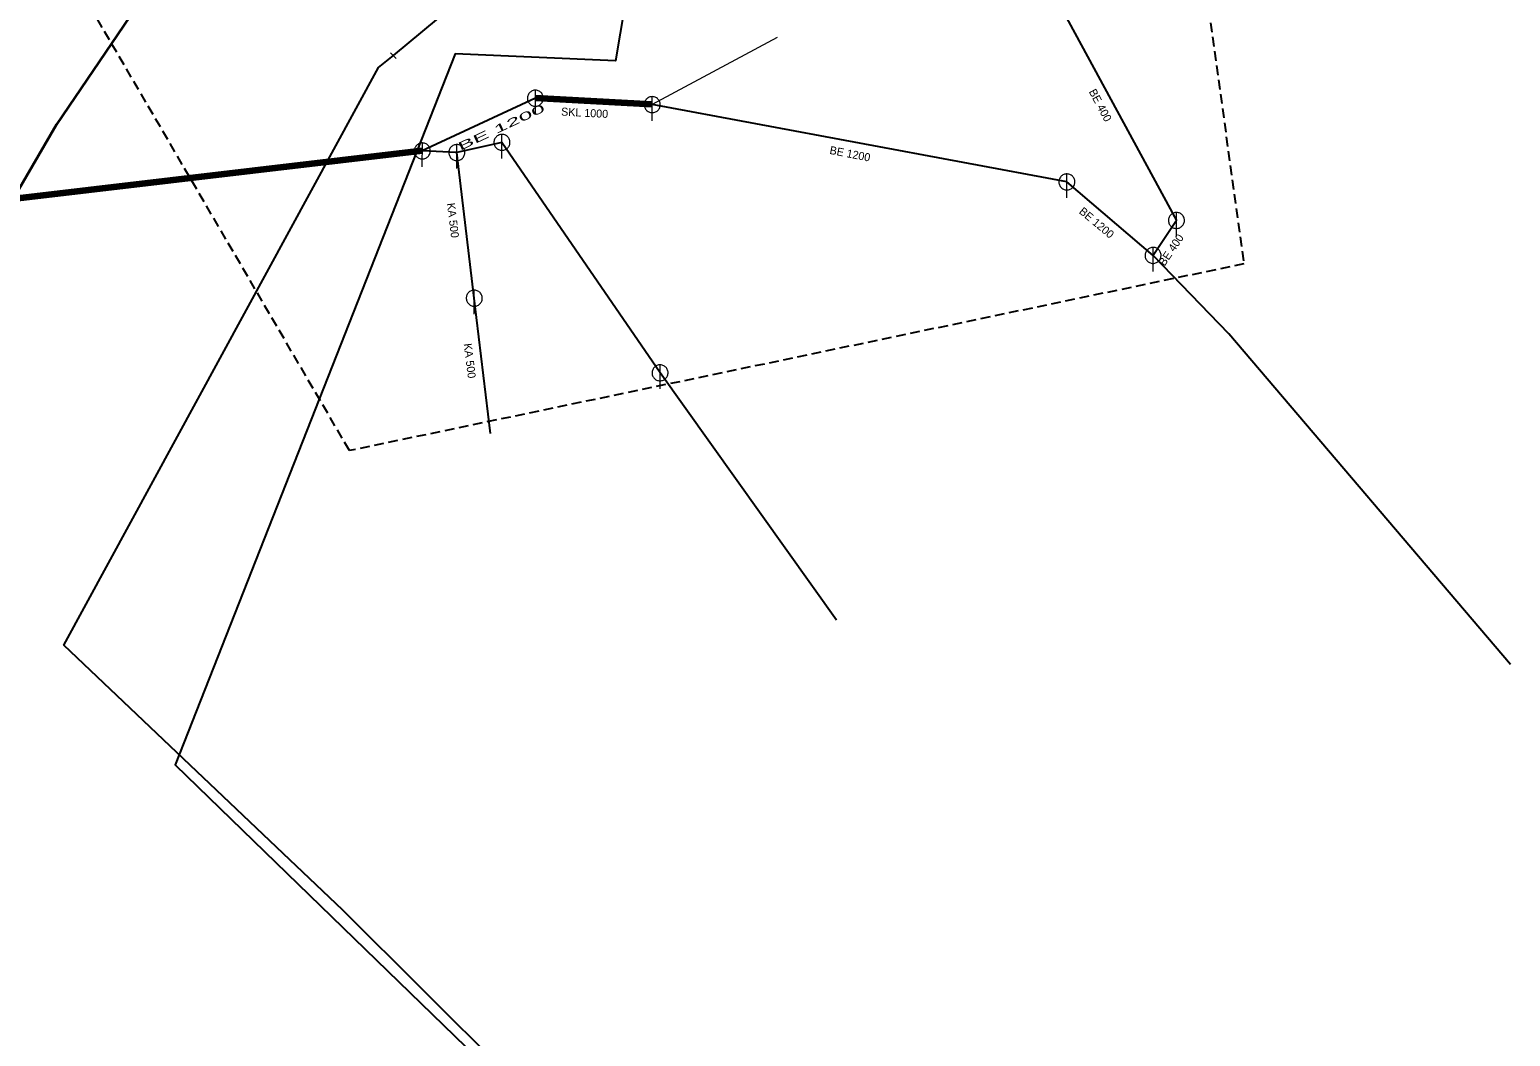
# Model space of a CAD drawing. Extents: x -687016 to -686065, y -974192 to -973552.
# Drawn here: x -686250.2 to -686065.2, y -974066.2 to -973940.5 of the extents above; entities that cross this region are included whole.
import ezdxf

# ---------------------------------------------------------------- set-up
doc = ezdxf.new("R2010")
doc.units = 0
doc.header["$LTSCALE"] = 0.4
doc.linetypes.add('MEDIUM_DASHED', pattern=[4.5, 3, -1.5])
doc.layers.add('1', color=7, linetype='Continuous')
for name, color, linetype, lineweight in [('11', 7, 'Continuous', 13), ('14', 7, 'Continuous', 25), ('17', 7, 'Continuous', 25), ('2', 7, 'Continuous', 106), ('22', 7, 'Continuous', 13), ('27', 7, 'Continuous', 158), ('34', 7, 'Continuous', 13), ('63', 7, 'MEDIUM_DASHED', 25)]:
    doc.layers.add(name, color=color, linetype=linetype, lineweight=lineweight)

msp = doc.modelspace()

# ---------------------------------------------------------------- linework, layer by layer
at = {"layer": '11'}
msp.add_line((-686156.82, -973941.526), (-686172.417, -973949.902), dxfattribs=at)
at = {"layer": '14'}
for p, q in [((-686187.015, -973949.094), (-686201.138, -973955.681)), ((-686172.417, -973949.902), (-686187.015, -973949.094)), ((-686120.612, -973959.55), (-686172.417, -973949.902)), ((-686201.138, -973955.681), (-686609.228, -974003.734)), ((-686196.83, -973955.883), (-686201.138, -973955.681)), ((-686191.19, -973954.607), (-686196.83, -973955.883)), ((-686194.649, -973974.06), (-686196.83, -973955.883)), ((-686171.44, -973983.379), (-686191.19, -973954.607)), ((-686109.848, -973968.717), (-686120.612, -973959.55)), ((-686106.927, -973964.355), (-686109.848, -973968.717)), ((-686192.641, -973990.944), (-686194.649, -973974.06)), ((-686149.399, -974014.248), (-686171.44, -973983.379))]:
    msp.add_line(p, q, dxfattribs=at)
for points in [[(-686124.153, -973921.386), (-686122.535, -973935.572), (-686106.927, -973964.355)], [(-686065.207, -974019.789), (-686100.367, -973978.502), (-686109.848, -973968.717)]]:
    msp.add_lwpolyline(points, dxfattribs=at)
at = {"layer": '17'}
for points in [[(-686204.755, -973943.783), (-686184.694, -973927.101), (-686177.797, -973880.398), (-686177.867, -973880.202), (-686191.62, -973832.066)], [(-686169.64, -973900.75), (-686177.013, -973944.41), (-686197.048, -973943.572), (-686232.018, -974032.331), (-686151.042, -974110.8), (-686189.024, -974153.642), (-686204.782, -974140.962), (-686246.709, -974191.881)], [(-686150.349, -974110.866), (-686211.068, -974050.449), (-686245.909, -974017.381), (-686206.618, -973945.282), (-686204.755, -973943.783)]]:
    msp.add_lwpolyline(points, dxfattribs=at)
at = {"layer": '17', "lineweight": 35}
msp.add_lwpolyline([(-686189.43, -973882.125), (-686219.828, -973916.223), (-686226.999, -973923.155), (-686246.828, -973952.39), (-686262.803, -973979.756), (-686282.183, -974011.51), (-686299.629, -974035.3), (-686327.833, -974075.543), (-686339.475, -974087.052), (-686408.796, -974118.009)], dxfattribs=at)
at = {"layer": '2'}
msp.add_line((-686172.417, -973949.902), (-686187.015, -973949.094), dxfattribs=at)
at = {"layer": '2', "lineweight": 100}
msp.add_line((-686172.417, -973949.902), (-686187.015, -973949.094), dxfattribs=at)
at = {"layer": '22'}
for p, q in [((-686187.015, -973951.094), (-686187.014, -973948.094)), ((-686172.417, -973951.902), (-686172.416, -973948.902)), ((-686191.19, -973956.607), (-686191.189, -973953.607)), ((-686201.138, -973957.681), (-686201.137, -973954.681)), ((-686196.83, -973957.883), (-686196.829, -973954.883)), ((-686120.612, -973961.55), (-686120.611, -973958.55)), ((-686106.927, -973966.355), (-686106.926, -973963.355)), ((-686109.848, -973970.717), (-686109.847, -973967.717)), ((-686194.649, -973976.06), (-686194.648, -973973.06)), ((-686171.44, -973985.379), (-686171.439, -973982.379))]:
    msp.add_line(p, q, dxfattribs=at)
for points in [[(-686186.015, -973949.094), (-686186.02, -973948.985), (-686186.038, -973948.877), (-686186.068, -973948.771), (-686186.108, -973948.67), (-686186.16, -973948.573), (-686186.222, -973948.483), (-686186.294, -973948.4), (-686186.374, -973948.326), (-686186.462, -973948.26), (-686186.556, -973948.205), (-686186.656, -973948.16), (-686186.761, -973948.127), (-686186.868, -973948.105), (-686186.977, -973948.095), (-686187.087, -973948.097), (-686187.195, -973948.111), (-686187.302, -973948.136), (-686187.405, -973948.173), (-686187.503, -973948.222), (-686187.595, -973948.28), (-686187.681, -973948.349), (-686187.758, -973948.426), (-686187.827, -973948.512), (-686187.886, -973948.604), (-686187.934, -973948.702), (-686187.971, -973948.805), (-686187.997, -973948.912), (-686188.011, -973949.02), (-686188.014, -973949.13), (-686188.004, -973949.239), (-686187.983, -973949.346), (-686187.949, -973949.45), (-686187.905, -973949.55), (-686187.85, -973949.645), (-686187.784, -973949.733), (-686187.71, -973949.813), (-686187.627, -973949.885), (-686187.537, -973949.947), (-686187.441, -973949.999), (-686187.339, -973950.04), (-686187.234, -973950.07), (-686187.126, -973950.088), (-686187.016, -973950.094), (-686186.907, -973950.088), (-686186.799, -973950.07), (-686186.694, -973950.041), (-686186.592, -973950), (-686186.495, -973949.948), (-686186.405, -973949.886), (-686186.322, -973949.815), (-686186.247, -973949.735), (-686186.182, -973949.647), (-686186.126, -973949.553), (-686186.082, -973949.453), (-686186.048, -973949.349), (-686186.026, -973949.241), (-686186.016, -973949.132)], [(-686171.417, -973949.902), (-686171.422, -973949.793), (-686171.44, -973949.685), (-686171.47, -973949.579), (-686171.51, -973949.478), (-686171.562, -973949.381), (-686171.624, -973949.291), (-686171.696, -973949.208), (-686171.776, -973949.134), (-686171.864, -973949.068), (-686171.958, -973949.013), (-686172.058, -973948.968), (-686172.163, -973948.935), (-686172.27, -973948.913), (-686172.379, -973948.903), (-686172.489, -973948.905), (-686172.597, -973948.919), (-686172.704, -973948.944), (-686172.807, -973948.981), (-686172.905, -973949.03), (-686172.997, -973949.088), (-686173.083, -973949.157), (-686173.16, -973949.234), (-686173.229, -973949.32), (-686173.288, -973949.412), (-686173.336, -973949.51), (-686173.373, -973949.613), (-686173.399, -973949.72), (-686173.413, -973949.828), (-686173.416, -973949.938), (-686173.406, -973950.047), (-686173.385, -973950.154), (-686173.351, -973950.258), (-686173.307, -973950.358), (-686173.252, -973950.453), (-686173.186, -973950.541), (-686173.112, -973950.621), (-686173.029, -973950.693), (-686172.939, -973950.755), (-686172.843, -973950.807), (-686172.741, -973950.848), (-686172.636, -973950.878), (-686172.528, -973950.896), (-686172.418, -973950.902), (-686172.309, -973950.896), (-686172.201, -973950.878), (-686172.096, -973950.849), (-686171.994, -973950.808), (-686171.897, -973950.756), (-686171.807, -973950.694), (-686171.724, -973950.623), (-686171.649, -973950.543), (-686171.584, -973950.455), (-686171.528, -973950.361), (-686171.484, -973950.261), (-686171.45, -973950.157), (-686171.428, -973950.049), (-686171.418, -973949.94)], [(-686190.19, -973954.607), (-686190.195, -973954.498), (-686190.213, -973954.39), (-686190.243, -973954.284), (-686190.283, -973954.183), (-686190.335, -973954.086), (-686190.397, -973953.996), (-686190.469, -973953.913), (-686190.549, -973953.839), (-686190.637, -973953.773), (-686190.731, -973953.718), (-686190.831, -973953.673), (-686190.936, -973953.64), (-686191.043, -973953.618), (-686191.152, -973953.608), (-686191.262, -973953.61), (-686191.37, -973953.624), (-686191.477, -973953.649), (-686191.58, -973953.686), (-686191.678, -973953.735), (-686191.77, -973953.793), (-686191.856, -973953.862), (-686191.933, -973953.939), (-686192.002, -973954.025), (-686192.061, -973954.117), (-686192.109, -973954.215), (-686192.146, -973954.318), (-686192.172, -973954.425), (-686192.186, -973954.533), (-686192.189, -973954.643), (-686192.179, -973954.752), (-686192.158, -973954.859), (-686192.124, -973954.963), (-686192.08, -973955.063), (-686192.025, -973955.158), (-686191.959, -973955.246), (-686191.885, -973955.326), (-686191.802, -973955.398), (-686191.712, -973955.46), (-686191.616, -973955.512), (-686191.514, -973955.553), (-686191.409, -973955.583), (-686191.301, -973955.601), (-686191.191, -973955.607), (-686191.082, -973955.601), (-686190.974, -973955.583), (-686190.869, -973955.554), (-686190.767, -973955.513), (-686190.67, -973955.461), (-686190.58, -973955.399), (-686190.497, -973955.328), (-686190.422, -973955.248), (-686190.357, -973955.16), (-686190.301, -973955.066), (-686190.257, -973954.966), (-686190.223, -973954.862), (-686190.201, -973954.754), (-686190.191, -973954.645)], [(-686200.138, -973955.681), (-686200.143, -973955.572), (-686200.161, -973955.464), (-686200.191, -973955.358), (-686200.231, -973955.257), (-686200.283, -973955.16), (-686200.345, -973955.07), (-686200.417, -973954.987), (-686200.497, -973954.913), (-686200.585, -973954.847), (-686200.679, -973954.792), (-686200.779, -973954.747), (-686200.884, -973954.714), (-686200.991, -973954.692), (-686201.1, -973954.682), (-686201.21, -973954.684), (-686201.318, -973954.698), (-686201.425, -973954.723), (-686201.528, -973954.76), (-686201.626, -973954.809), (-686201.718, -973954.867), (-686201.804, -973954.936), (-686201.881, -973955.013), (-686201.95, -973955.099), (-686202.009, -973955.191), (-686202.057, -973955.289), (-686202.094, -973955.392), (-686202.12, -973955.499), (-686202.134, -973955.607), (-686202.137, -973955.717), (-686202.127, -973955.826), (-686202.106, -973955.933), (-686202.072, -973956.037), (-686202.028, -973956.137), (-686201.973, -973956.232), (-686201.907, -973956.32), (-686201.833, -973956.4), (-686201.75, -973956.472), (-686201.66, -973956.534), (-686201.564, -973956.586), (-686201.462, -973956.627), (-686201.357, -973956.657), (-686201.249, -973956.675), (-686201.139, -973956.681), (-686201.03, -973956.675), (-686200.922, -973956.657), (-686200.817, -973956.628), (-686200.715, -973956.587), (-686200.618, -973956.535), (-686200.528, -973956.473), (-686200.445, -973956.402), (-686200.37, -973956.322), (-686200.305, -973956.234), (-686200.249, -973956.14), (-686200.205, -973956.04), (-686200.171, -973955.936), (-686200.149, -973955.828), (-686200.139, -973955.719)], [(-686195.83, -973955.883), (-686195.835, -973955.774), (-686195.853, -973955.666), (-686195.883, -973955.56), (-686195.923, -973955.459), (-686195.975, -973955.362), (-686196.037, -973955.272), (-686196.109, -973955.189), (-686196.189, -973955.115), (-686196.277, -973955.049), (-686196.371, -973954.994), (-686196.471, -973954.949), (-686196.576, -973954.916), (-686196.683, -973954.894), (-686196.792, -973954.884), (-686196.902, -973954.886), (-686197.01, -973954.9), (-686197.117, -973954.925), (-686197.22, -973954.962), (-686197.318, -973955.011), (-686197.41, -973955.069), (-686197.496, -973955.138), (-686197.573, -973955.215), (-686197.642, -973955.301), (-686197.701, -973955.393), (-686197.749, -973955.491), (-686197.786, -973955.594), (-686197.812, -973955.701), (-686197.826, -973955.809), (-686197.829, -973955.919), (-686197.819, -973956.028), (-686197.798, -973956.135), (-686197.764, -973956.239), (-686197.72, -973956.339), (-686197.665, -973956.434), (-686197.599, -973956.522), (-686197.525, -973956.602), (-686197.442, -973956.674), (-686197.352, -973956.736), (-686197.256, -973956.788), (-686197.154, -973956.829), (-686197.049, -973956.859), (-686196.941, -973956.877), (-686196.831, -973956.883), (-686196.722, -973956.877), (-686196.614, -973956.859), (-686196.509, -973956.83), (-686196.407, -973956.789), (-686196.31, -973956.737), (-686196.22, -973956.675), (-686196.137, -973956.604), (-686196.062, -973956.524), (-686195.997, -973956.436), (-686195.941, -973956.342), (-686195.897, -973956.242), (-686195.863, -973956.138), (-686195.841, -973956.03), (-686195.831, -973955.921)], [(-686119.612, -973959.55), (-686119.617, -973959.441), (-686119.635, -973959.333), (-686119.665, -973959.227), (-686119.705, -973959.126), (-686119.757, -973959.029), (-686119.819, -973958.939), (-686119.891, -973958.856), (-686119.971, -973958.782), (-686120.059, -973958.716), (-686120.153, -973958.661), (-686120.253, -973958.616), (-686120.358, -973958.583), (-686120.465, -973958.561), (-686120.574, -973958.551), (-686120.684, -973958.553), (-686120.792, -973958.567), (-686120.899, -973958.592), (-686121.002, -973958.629), (-686121.1, -973958.678), (-686121.192, -973958.736), (-686121.278, -973958.805), (-686121.355, -973958.882), (-686121.424, -973958.968), (-686121.483, -973959.06), (-686121.531, -973959.158), (-686121.568, -973959.261), (-686121.594, -973959.368), (-686121.608, -973959.476), (-686121.611, -973959.586), (-686121.601, -973959.695), (-686121.58, -973959.802), (-686121.546, -973959.906), (-686121.502, -973960.006), (-686121.447, -973960.101), (-686121.381, -973960.189), (-686121.307, -973960.269), (-686121.224, -973960.341), (-686121.134, -973960.403), (-686121.038, -973960.455), (-686120.936, -973960.496), (-686120.831, -973960.526), (-686120.723, -973960.544), (-686120.613, -973960.55), (-686120.504, -973960.544), (-686120.396, -973960.526), (-686120.291, -973960.497), (-686120.189, -973960.456), (-686120.092, -973960.404), (-686120.002, -973960.342), (-686119.919, -973960.271), (-686119.844, -973960.191), (-686119.779, -973960.103), (-686119.723, -973960.009), (-686119.679, -973959.909), (-686119.645, -973959.805), (-686119.623, -973959.697), (-686119.613, -973959.588)], [(-686105.927, -973964.355), (-686105.932, -973964.246), (-686105.95, -973964.138), (-686105.98, -973964.032), (-686106.02, -973963.931), (-686106.072, -973963.834), (-686106.134, -973963.744), (-686106.206, -973963.661), (-686106.286, -973963.587), (-686106.374, -973963.521), (-686106.468, -973963.466), (-686106.568, -973963.421), (-686106.673, -973963.388), (-686106.78, -973963.366), (-686106.889, -973963.356), (-686106.999, -973963.358), (-686107.107, -973963.372), (-686107.214, -973963.397), (-686107.317, -973963.434), (-686107.415, -973963.483), (-686107.507, -973963.541), (-686107.593, -973963.61), (-686107.67, -973963.687), (-686107.739, -973963.773), (-686107.798, -973963.865), (-686107.846, -973963.963), (-686107.883, -973964.066), (-686107.909, -973964.173), (-686107.923, -973964.281), (-686107.926, -973964.391), (-686107.916, -973964.5), (-686107.895, -973964.607), (-686107.861, -973964.711), (-686107.817, -973964.811), (-686107.762, -973964.906), (-686107.696, -973964.994), (-686107.622, -973965.074), (-686107.539, -973965.146), (-686107.449, -973965.208), (-686107.353, -973965.26), (-686107.251, -973965.301), (-686107.146, -973965.331), (-686107.038, -973965.349), (-686106.928, -973965.355), (-686106.819, -973965.349), (-686106.711, -973965.331), (-686106.606, -973965.302), (-686106.504, -973965.261), (-686106.407, -973965.209), (-686106.317, -973965.147), (-686106.234, -973965.076), (-686106.159, -973964.996), (-686106.094, -973964.908), (-686106.038, -973964.814), (-686105.994, -973964.714), (-686105.96, -973964.61), (-686105.938, -973964.502), (-686105.928, -973964.393)], [(-686108.848, -973968.717), (-686108.853, -973968.608), (-686108.871, -973968.5), (-686108.901, -973968.394), (-686108.941, -973968.293), (-686108.993, -973968.196), (-686109.055, -973968.106), (-686109.127, -973968.023), (-686109.207, -973967.949), (-686109.295, -973967.883), (-686109.389, -973967.828), (-686109.489, -973967.783), (-686109.594, -973967.75), (-686109.701, -973967.728), (-686109.81, -973967.718), (-686109.92, -973967.72), (-686110.028, -973967.734), (-686110.135, -973967.759), (-686110.238, -973967.796), (-686110.336, -973967.845), (-686110.428, -973967.903), (-686110.514, -973967.972), (-686110.591, -973968.049), (-686110.66, -973968.135), (-686110.719, -973968.227), (-686110.767, -973968.325), (-686110.804, -973968.428), (-686110.83, -973968.535), (-686110.844, -973968.643), (-686110.847, -973968.753), (-686110.837, -973968.862), (-686110.816, -973968.969), (-686110.782, -973969.073), (-686110.738, -973969.173), (-686110.683, -973969.268), (-686110.617, -973969.356), (-686110.543, -973969.436), (-686110.46, -973969.508), (-686110.37, -973969.57), (-686110.274, -973969.622), (-686110.172, -973969.663), (-686110.067, -973969.693), (-686109.959, -973969.711), (-686109.849, -973969.717), (-686109.74, -973969.711), (-686109.632, -973969.693), (-686109.527, -973969.664), (-686109.425, -973969.623), (-686109.328, -973969.571), (-686109.238, -973969.509), (-686109.155, -973969.438), (-686109.08, -973969.358), (-686109.015, -973969.27), (-686108.959, -973969.176), (-686108.915, -973969.076), (-686108.881, -973968.972), (-686108.859, -973968.864), (-686108.849, -973968.755)], [(-686193.649, -973974.06), (-686193.654, -973973.951), (-686193.672, -973973.843), (-686193.702, -973973.737), (-686193.742, -973973.636), (-686193.794, -973973.539), (-686193.856, -973973.449), (-686193.928, -973973.366), (-686194.008, -973973.292), (-686194.096, -973973.226), (-686194.19, -973973.171), (-686194.29, -973973.126), (-686194.395, -973973.093), (-686194.502, -973973.071), (-686194.611, -973973.061), (-686194.721, -973973.063), (-686194.829, -973973.077), (-686194.936, -973973.102), (-686195.039, -973973.139), (-686195.137, -973973.188), (-686195.229, -973973.246), (-686195.315, -973973.315), (-686195.392, -973973.392), (-686195.461, -973973.478), (-686195.52, -973973.57), (-686195.568, -973973.668), (-686195.605, -973973.771), (-686195.631, -973973.878), (-686195.645, -973973.986), (-686195.648, -973974.096), (-686195.638, -973974.205), (-686195.617, -973974.312), (-686195.583, -973974.416), (-686195.539, -973974.516), (-686195.484, -973974.611), (-686195.418, -973974.699), (-686195.344, -973974.779), (-686195.261, -973974.851), (-686195.171, -973974.913), (-686195.075, -973974.965), (-686194.973, -973975.006), (-686194.868, -973975.036), (-686194.76, -973975.054), (-686194.65, -973975.06), (-686194.541, -973975.054), (-686194.433, -973975.036), (-686194.328, -973975.007), (-686194.226, -973974.966), (-686194.129, -973974.914), (-686194.039, -973974.852), (-686193.956, -973974.781), (-686193.881, -973974.701), (-686193.816, -973974.613), (-686193.76, -973974.519), (-686193.716, -973974.419), (-686193.682, -973974.315), (-686193.66, -973974.207), (-686193.65, -973974.098)], [(-686170.44, -973983.379), (-686170.445, -973983.27), (-686170.463, -973983.162), (-686170.493, -973983.056), (-686170.533, -973982.955), (-686170.585, -973982.858), (-686170.647, -973982.768), (-686170.719, -973982.685), (-686170.799, -973982.611), (-686170.887, -973982.545), (-686170.981, -973982.49), (-686171.081, -973982.445), (-686171.186, -973982.412), (-686171.293, -973982.39), (-686171.402, -973982.38), (-686171.512, -973982.382), (-686171.62, -973982.396), (-686171.727, -973982.421), (-686171.83, -973982.458), (-686171.928, -973982.507), (-686172.02, -973982.565), (-686172.106, -973982.634), (-686172.183, -973982.711), (-686172.252, -973982.797), (-686172.311, -973982.889), (-686172.359, -973982.987), (-686172.396, -973983.09), (-686172.422, -973983.197), (-686172.436, -973983.305), (-686172.439, -973983.415), (-686172.429, -973983.524), (-686172.408, -973983.631), (-686172.374, -973983.735), (-686172.33, -973983.835), (-686172.275, -973983.93), (-686172.209, -973984.018), (-686172.135, -973984.098), (-686172.052, -973984.17), (-686171.962, -973984.232), (-686171.866, -973984.284), (-686171.764, -973984.325), (-686171.659, -973984.355), (-686171.551, -973984.373), (-686171.441, -973984.379), (-686171.332, -973984.373), (-686171.224, -973984.355), (-686171.119, -973984.326), (-686171.017, -973984.285), (-686170.92, -973984.233), (-686170.83, -973984.171), (-686170.747, -973984.1), (-686170.672, -973984.02), (-686170.607, -973983.932), (-686170.551, -973983.838), (-686170.507, -973983.738), (-686170.473, -973983.634), (-686170.451, -973983.526), (-686170.441, -973983.417)]]:
    msp.add_lwpolyline(points, close=True, dxfattribs=at)
at = {"layer": '27'}
msp.add_lwpolyline([(-686201.138, -973955.681), (-686609.228, -974003.734), (-687016.03, -974132.098)], dxfattribs=at)
msp.add_lwpolyline([(-686201.138, -973955.681), (-686609.228, -974003.734), (-687016.03, -974132.098)], dxfattribs=at)
at = {"layer": '34'}
msp.add_line((-686205.1, -973943.421), (-686204.41, -973944.145), dxfattribs=at)
at = {"layer": '63'}
msp.add_lwpolyline([(-686318.355, -973808.199), (-686197.373, -973790.916), (-686197.373, -973790.916), (-686115.78, -973845.177), (-686115.78, -973845.177), (-686098.497, -973969.777), (-686098.497, -973969.777), (-686210.235, -973993.089), (-686210.235, -973993.089)], close=True, dxfattribs=at)

# ---------------------------------------------------------------- texts
at = {"layer": '1'}
for s, rotation, p in [('BE 400', 298, (-686117.906, -973948.272)), ('SKL 1000', 357, (-686183.819, -973951.259)), ('BE 1200 ', 349, (-686150.318, -973956.036)), ('KA 500', 277, (-686198.067, -973962.228)), ('BE 1200 ', 320, (-686119.181, -973963.375)), ('BE 400', 56, (-686108.407, -973970.132)), ('KA 500', 277, (-686195.97, -973979.758))]:
    msp.add_text(s, height=1, rotation=rotation, dxfattribs=at).set_placement(p)
at = {"layer": '1', "width": 2.3}
msp.add_text('BE 1200 ', height=1, rotation=25, dxfattribs=at).set_placement((-686196.408, -973955.665))

doc.saveas('drawing.dxf')
